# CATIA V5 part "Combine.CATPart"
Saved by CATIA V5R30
Part number: Part1
Bounding box of the stored display mesh (mm): x 0 to 48.303, y -48.737 to 82.157, z 0 to 68.503
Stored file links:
  D:\PROJECTS\CATIA V56R 2020\Resources\Parts File\c17_catia_v6_6r2020_prt\Combine.CATPart
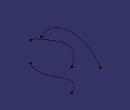
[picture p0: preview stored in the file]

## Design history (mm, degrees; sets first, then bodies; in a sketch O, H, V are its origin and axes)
Set1
  Sketch1 on xy-plane, origin (0, 0, 0), H (1, 0, 0), V (0, 1, 0)
    spline S1 through (48.3033, 66.5608) (25.8768, 40.109) (39.1026, 7.9068) (36.515, -36.6587)
  Sketch2 on yz-plane, origin (0, 0, 0), H (0, 1, 0), V (0, 0, 1)
    arc A1 centre (18.404, -5.761) radius 74.2849 from (-48.7369, 26.0251) to (82.1569, 32.368) cw
  Combine1: Curve1 Sketch2, Curve2 Sketch1
Body1 (main body)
